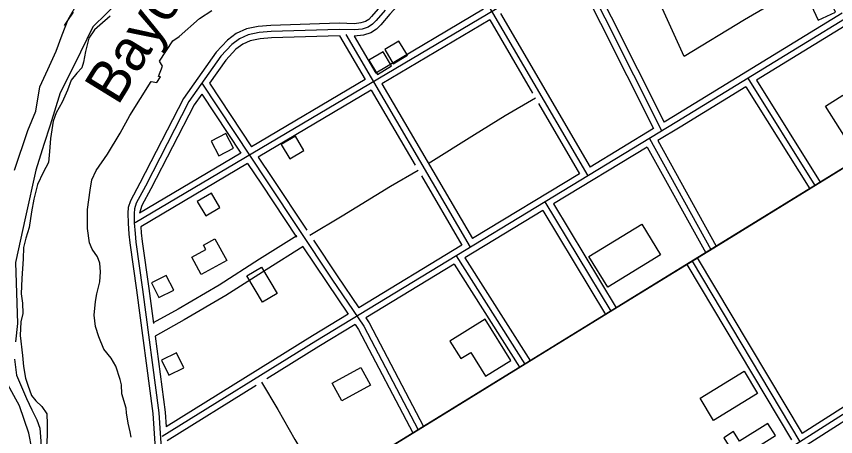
# Model space of a CAD drawing. Extents: x 3297772 to 3335630, y 634068 to 659439.
# Drawn here: x 3308401 to 3310382, y 649082 to 650098 of the extents above; entities that cross this region are included whole.
import ezdxf

# ---------------------------------------------------------------- set-up
doc = ezdxf.new("R2010")
doc.units = 0
for name, color, linetype in [('V-BLDG-OTLN', 7, 'Continuous'), ('V-DTCH-CNTR', 7, 'Continuous'), ('V-RIVR-IDEN', 7, 'Continuous'), ('V-ROAD-CNTR', 7, 'Continuous'), ('V-SITE-OTLN', 7, 'Continuous'), ('V-SITE-VEGE', 7, 'Continuous'), ('V-TOPO-SHOR', 7, 'Continuous')]:
    doc.layers.add(name, color=color, linetype=linetype)

msp = doc.modelspace()

# ---------------------------------------------------------------- linework, layer by layer
at = {"layer": 'V-BLDG-OTLN'}
for points in [[(3310300.2693621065, 650174.3976244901), (3310339.004284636, 650089.4497943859), (3310381.238200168, 650108.7077558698), (3310342.503277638, 650193.655585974)], [(3309312.2503381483, 649983.817005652), (3309346.6042694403, 650004.3049646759), (3309326.1163104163, 650038.6598959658), (3309291.7623791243, 650018.1719369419)], [(3309273.926414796, 649958.0390572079), (3309308.2803460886, 649978.527016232), (3309287.792387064, 650012.8819475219), (3309253.4384557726, 649992.393988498)], [(3310536.719889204, 649841.0272912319), (3310426.5151096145, 649771.591430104), (3310357.2882480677, 649881.4642103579), (3310399.2181642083, 649907.882157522), (3310430.605101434, 649858.066257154), (3310498.8809648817, 649901.084171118)], [(3308890.806181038, 649760.702451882), (3308926.246110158, 649779.2484147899), (3308907.6991472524, 649814.6893439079), (3308872.259218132, 649796.142381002)], [(3309076.1628103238, 649808.5883561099), (3309041.6768792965, 649788.322396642), (3309061.941838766, 649753.8364656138), (3309096.428769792, 649774.1014250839)], [(3308873.121216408, 649670.5426322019), (3308838.6352853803, 649650.2766727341), (3308858.90024485, 649615.7907417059), (3308893.387175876, 649636.0557011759)], [(3309958.355045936, 649521.1839309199), (3309830.670301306, 649443.2360868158), (3309785.346391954, 649517.479938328), (3309913.030136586, 649595.4277824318)], [(3308909.7231432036, 649507.71395786), (3308848.24026617, 649473.94902539), (3308825.0623125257, 649516.1549409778), (3308859.012244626, 649534.7989036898), (3308853.277256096, 649545.241882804), (3308880.8102010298, 649560.3618525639)], [(3308993.54497556, 649491.5009902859), (3309031.3838998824, 649427.7011178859), (3308996.0379705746, 649406.7381598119), (3308958.1990462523, 649470.5380322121)], [(3308727.9005068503, 649453.8840655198), (3308745.746471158, 649418.086137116), (3308781.544399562, 649435.9311014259), (3308763.699435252, 649471.7300298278)], [(3309596.23877017, 649265.5584421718), (3309534.045894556, 649365.5672421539), (3309449.310064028, 649312.872347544), (3309475.60401144, 649270.5894321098), (3309499.49896365, 649285.448402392), (3309535.394891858, 649227.7235178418)], [(3308752.28045809, 649266.378440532), (3308770.1264223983, 649230.5805121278), (3308805.924350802, 649248.4254764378), (3308788.079386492, 649284.22440484)], [(3309257.065448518, 649206.627560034), (3309188.227586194, 649168.6956358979), (3309164.818633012, 649211.1775509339), (3309233.656495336, 649249.10947507)], [(3310193.070576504, 649186.2706007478), (3310086.691789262, 649121.062731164), (3310053.806855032, 649174.710623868), (3310160.185642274, 649239.9184934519)], [(3310218.0345265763, 649113.8327456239), (3310149.2906640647, 649070.8638315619), (3310134.761693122, 649094.106785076), (3310110.9797406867, 649079.2408148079), (3310157.84764695, 649004.263964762), (3310178.125606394, 649016.9389394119), (3310164.26763411, 649039.1098950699), (3310236.5144896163, 649084.2678047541)]]:
    msp.add_lwpolyline(points, close=True, dxfattribs=at)
at = {"layer": 'V-DTCH-CNTR'}
msp.add_lwpolyline([(3308538.738, 650108.683), (3308524.932, 650088.662), (3308516.4960000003, 650076.343)], dxfattribs=at)
at = {"layer": 'V-ROAD-CNTR'}
for points in [[(3312568.9648247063, 651419.2411347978), (3311740.8984808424, 650919.1061350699), (3310719.21652421, 650286.2024008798), (3309997.8719669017, 649843.5352862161), (3309124.83971297, 649312.9013474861), (3308753.5614555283, 649081.90480948)], [(3312695.4435717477, 651149.2656747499), (3311525.301912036, 650438.1720969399), (3310854.68125328, 650011.558950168), (3309964.594033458, 649463.1000470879), (3308763.833434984, 648723.4155264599)], [(3312939.259084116, 650719.7405338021), (3312147.8886668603, 650226.4545203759), (3311603.3287559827, 649890.6091920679), (3310922.80111704, 649468.348036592), (3310057.579847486, 648917.3251386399), (3309400.102162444, 648502.041969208), (3308809.789343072, 648126.674719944), (3308064.599833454, 647651.8196696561), (3307615.6257314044, 647365.3602425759), (3307608.5777455, 647358.1752569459), (3307605.153752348, 647352.5692681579), (3307604.129754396, 647346.629280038), (3307606.361749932, 647341.7572897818), (3307617.461727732, 647320.5463322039), (3307621.65271935, 647311.931349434), (3307623.69271527, 647303.7813657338), (3307622.4197178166, 647297.7103778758), (3307620.646721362, 647291.379390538), (3307614.8467329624, 647284.846403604), (3307604.638753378, 647278.2334168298), (3306995.5399715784, 646891.920189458)], [(3308752.507457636, 648666.5346402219), (3308768.289426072, 648701.1635709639), (3308774.102414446, 648727.3205186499), (3308854.756253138, 648778.183416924), (3309003.575955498, 648871.1002310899), (3309462.9030368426, 649154.052665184), (3309689.957582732, 649293.920385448), (3309910.267142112, 649429.6341140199), (3310107.8487469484, 649551.3718705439), (3310370.686221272, 649713.3285466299), (3310640.1676823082, 649879.3792145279), (3310865.89123086, 650018.689935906), (3311087.3317879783, 650159.5586541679), (3311313.702335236, 650303.5643661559), (3311454.208054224, 650392.9451873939), (3311582.125798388, 650472.7040278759), (3311736.615489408, 650566.5868401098), (3311915.161132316, 650675.088623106), (3312000.5909614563, 650727.004519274)], [(3309727.1325083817, 650621.3827305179), (3309855.7092512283, 650316.845339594), (3309858.022246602, 650307.566358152), (3309857.3322479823, 650304.026365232), (3309852.731257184, 650293.9893853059), (3309843.959274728, 650284.6304040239), (3308688.2105862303, 649598.730775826)], [(3309446.96906871, 650288.7063958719), (3309782.5763974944, 649712.6775479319)], [(3309445.3200720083, 650261.7404498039), (3309427.4661077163, 650238.240496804), (3309303.930354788, 650103.4887663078), (3309282.076398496, 650077.9678173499), (3309271.8344189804, 650067.4678383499), (3309257.726447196, 650058.8808555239), (3309240.385481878, 650053.0958670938), (3309217.877526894, 650050.4698723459)], [(3309755.2474521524, 650231.98250932), (3309961.2380401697, 649821.054331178)], [(3309774.91841281, 650226.2135208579), (3309967.2730281, 649842.489288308)], [(3309749.054464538, 650210.8645515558), (3309941.550079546, 649826.8563195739)], [(3309281.4743997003, 650123.386726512), (3309259.9224428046, 650098.219776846), (3309253.002456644, 650091.125791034), (3309245.020472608, 650086.2668007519), (3309233.831494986, 650082.533808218), (3309218.447525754, 650080.739811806), (3309181.400599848, 650081.6648099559), (3309016.166930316, 650076.509820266), (3308986.088990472, 650074.0018252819), (3308957.229048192, 650068.146836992), (3308932.963096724, 650057.2208588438), (3308911.7701391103, 650041.16289096), (3308884.124194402, 650011.5209502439), (3308805.602351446, 649900.067173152), (3308699.734563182, 649694.9775833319), (3308676.9696087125, 649652.3696685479), (3308671.822619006, 649636.0897011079), (3308670.657621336, 649622.1127290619), (3308671.1636203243, 649597.8727775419), (3308673.1256164, 649571.8668295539), (3308675.181612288, 649550.2618727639), (3308691.4425797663, 649435.773101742), (3308731.0315005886, 649137.6236980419), (3308740.609481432, 648991.5169902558)], [(3309292.702377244, 650113.4377464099), (3309270.9994206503, 650088.0937970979), (3309262.418437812, 650079.2968146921), (3309251.3734599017, 650072.573828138), (3309237.108488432, 650067.814837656), (3309219.132524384, 650065.7178418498), (3309181.447599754, 650066.658839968), (3309017.0249286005, 650061.5288502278), (3308988.210986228, 650059.1268550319), (3308961.857038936, 650053.779865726), (3308940.669081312, 650044.239884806), (3308921.858118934, 650029.986913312), (3308895.794171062, 650002.0419692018), (3308818.4583257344, 649892.2711887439), (3308713.014536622, 649688.002597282), (3308690.8535809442, 649646.524680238), (3308686.631589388, 649633.1697069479), (3308685.67059131, 649621.6447299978), (3308686.151590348, 649598.5937761), (3308688.071586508, 649573.1418270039), (3308690.081582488, 649552.027869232), (3308706.303550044, 649437.815097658), (3308745.9664707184, 649139.1026950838), (3308755.617451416, 648991.8879895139)], [(3309530.2819020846, 650115.9157414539), (3309269.8944228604, 649961.384050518)], [(3309571.182820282, 650105.3057626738), (3309787.844386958, 649733.4325064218)], [(3310397.51716761, 650106.384760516), (3309990.053982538, 649856.336260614), (3309967.2730281, 649842.489288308)], [(3309545.384871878, 650089.993793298), (3309285.0213926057, 649935.476102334)], [(3309545.382871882, 650089.993793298), (3309648.6587867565, 649912.7336634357)], [(3310404.715153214, 650075.603822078), (3310190.111582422, 649943.90808547)], [(3309182.42959779, 650051.681869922), (3309017.882926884, 650046.54788019), (3308990.332981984, 650044.2518847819), (3308966.48502968, 650039.41289446), (3308948.3750659, 650031.2589107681), (3308931.946098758, 650018.810935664), (3308907.4641477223, 649992.56298816), (3308867.9802266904, 649936.51810025)], [(3309182.42959779, 650051.681869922), (3309244.09447446, 649946.072081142)], [(3309197.998566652, 650054.7668637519), (3309498.5409655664, 649540.03889321)], [(3309217.877526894, 650050.4698723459), (3309269.893422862, 649961.38305052)], [(3309244.095474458, 649946.0730811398), (3308969.534023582, 649783.1304070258)], [(3310169.375623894, 649948.782075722), (3310331.614299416, 649689.2525947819)], [(3308849.816263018, 649936.7800997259), (3309006.1809502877, 649700.6055720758), (3309164.018634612, 649462.7830477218), (3309241.0794804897, 649348.9392754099), (3309372.525217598, 649098.3777765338)], [(3308867.979226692, 649936.517100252), (3308969.534023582, 649783.129407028)], [(3309285.0203926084, 649935.476102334), (3309503.796955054, 649560.7868517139)], [(3310164.541633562, 649928.216116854), (3310005.689951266, 649830.7343118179), (3309951.4770596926, 649797.7823777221)], [(3310164.541633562, 649928.2171168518), (3310318.8383249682, 649681.3916105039)], [(3310190.111582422, 649943.9090854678), (3310344.394273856, 649697.107579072)], [(3308849.431263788, 649910.190152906), (3308831.314300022, 649884.475204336), (3308726.2945100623, 649681.0276112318), (3308704.737553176, 649640.679691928), (3308699.0185646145, 649622.587728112)], [(3308849.431263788, 649910.190152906), (3308943.704075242, 649767.7994376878)], [(3309259.2224442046, 649920.165132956), (3308986.1149904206, 649758.0854571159)], [(3309259.2214442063, 649920.165132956), (3309365.5312364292, 649738.0920845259)], [(3309655.7991416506, 649900.4781415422), (3309582.829, 649857.476), (3309508.609, 649812.221), (3309396.805715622, 649741.37142523)], [(3309663.303262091, 649887.5982618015), (3309762.20343824, 649717.84853759)], [(3309941.550079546, 649826.8563195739), (3309787.844386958, 649733.4325064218)], [(3309931.375099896, 649803.11836705), (3310080.2128022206, 649534.3429046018)], [(3309951.4760596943, 649797.7833777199), (3310092.926776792, 649542.3458885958)], [(3308943.70507524, 649767.800437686), (3308699.0185646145, 649622.587728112)], [(3309925.820111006, 649782.1884089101), (3309699.3305639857, 649644.5266842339)], [(3309925.819111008, 649782.1884089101), (3310067.4678277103, 649526.392920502)], [(3308986.1149904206, 649758.0854571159), (3309018.683925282, 649708.8935555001), (3309103.5013239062, 649581.0941963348)], [(3308960.28504208, 649742.7554877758), (3308701.887558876, 649589.405794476)], [(3308960.28504208, 649742.7554877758), (3308993.677975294, 649692.3175886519), (3309078.474173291, 649564.5510229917)], [(3309110.993708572, 649569.2080000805), (3309188.433, 649615.75), (3309305.66, 649687.389), (3309372.7168153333, 649726.3903387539)], [(3309380.2151275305, 649712.9434998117), (3309478.1570063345, 649545.201882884)], [(3309762.2044382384, 649717.84853759), (3309503.796955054, 649560.7868517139)], [(3309678.772605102, 649649.5846741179), (3309838.054286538, 649385.1492029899)], [(3309673.6946152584, 649628.945715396), (3309484.951992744, 649514.2259448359)], [(3309673.69361526, 649628.9447153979), (3309825.2733121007, 649377.297218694)], [(3309699.3305639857, 649644.5266842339), (3309850.774261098, 649393.1021870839)], [(3308701.887558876, 649589.405794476), (3308703.017556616, 649574.4168244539), (3308704.9815526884, 649553.7938657), (3308721.164520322, 649439.8570935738), (3308732.382426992, 649355.3703372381)], [(3309078.810966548, 649567.1076163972), (3308989.044743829, 649510.722225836), (3308891.810838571, 649448.5592807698), (3308792.2404384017, 649389.967542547), (3308732.205029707, 649356.7063905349)], [(3309119.4209402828, 649557.1071747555), (3309176.4786096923, 649471.135031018), (3309228.89450486, 649393.7001858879)], [(3309094.444814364, 649541.5004176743), (3309005.103256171, 649485.3817741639), (3308907.5031614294, 649422.9847192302), (3308807.119561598, 649363.9144574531), (3308736.4467877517, 649324.7599330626)], [(3309094.067769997, 649541.055390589), (3309151.558659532, 649454.431064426), (3309203.227556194, 649378.0992170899)], [(3309478.1580063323, 649545.2028828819), (3309228.895504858, 649393.7001858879)], [(3309464.080034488, 649519.0939350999), (3309630.5477015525, 649257.3224586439)], [(3309484.9509927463, 649514.226944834), (3309643.91367482, 649264.2574447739)], [(3310047.238868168, 649514.0609451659), (3310300.384361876, 649089.7417938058)], [(3309459.3110440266, 649498.6419760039), (3309245.731471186, 649368.826235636)], [(3309459.3100440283, 649498.6419760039), (3309617.7527271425, 649249.48947431)], [(3310021.750919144, 649498.22897683), (3310275.069412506, 649073.620826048)], [(3310034.48289368, 649506.1649609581), (3310295.416371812, 649068.7928357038)], [(3310791.862378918, 649402.742167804), (3310300.385361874, 649089.7417938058)], [(3309203.22955619, 649378.100217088), (3309116.9817286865, 649325.6783219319), (3308763.1964362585, 649105.5657621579)], [(3309220.065522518, 649353.2262668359), (3309132.6976972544, 649300.1243730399), (3309006.337444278, 649221.5071959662)], [(3309220.063522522, 649353.227266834), (3309228.186506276, 649341.227290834), (3309359.64424336, 649090.6427920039)], [(3309245.730471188, 649368.8282356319), (3309253.9724547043, 649356.651259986), (3309385.1981922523, 649106.5087602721)], [(3308736.4747761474, 649324.5491407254), (3308760.9014408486, 649140.581692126), (3308763.1964362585, 649105.5657621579)], [(3308993.4169608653, 649213.4684978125), (3309033.2830000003, 649147.684), (3309074.1890000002, 649074.435), (3309144.3741436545, 648957.8340459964)], [(3308981.1340152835, 649205.8264546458), (3308765.422431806, 649071.6178300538)], [(3310462.1490383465, 649157.1946589), (3310199.2035642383, 648989.7359938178)]]:
    msp.add_lwpolyline(points, dxfattribs=at)
at = {"layer": 'V-SITE-OTLN'}
msp.add_lwpolyline([(3310348.162, 650199.7660000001), (3310161.554, 650089.801), (3310015.049, 650001.524), (3309915.051, 650223.658), (3309837.522, 650402.606), (3309754.568, 650592.351), (3309970.535, 650687.706), (3310105.517, 650746.627), (3310191.566, 650552.256), (3310298.545, 650313.15)], close=True, dxfattribs=at)
at = {"layer": 'V-SITE-VEGE'}
for points in [[(3308396.664, 649726.737), (3308428.596, 649822.598), (3308448.247, 649869.301), (3308458.071, 649928.2930000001), (3308477.722, 649970.079), (3308497.37, 650014.324), (3308512.108, 650053.652), (3308526.845, 650090.522), (3308551.409, 650134.765)], [(3308652.113, 650137.22), (3308585.795, 650073.312), (3308541.582, 649982.367), (3308507.194, 649913.542), (3308482.633, 649834.888), (3308467.895, 649788.186), (3308448.245, 649726.735), (3308423.683, 649613.665), (3308399.119, 649503.057), (3308404.035, 649355.578), (3308399.119, 649311.333)], [(3308396.664, 649269.5480000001), (3308401.577, 649230.22), (3308426.139, 649173.687), (3308438.421, 649146.65), (3308450.7, 649122.0700000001), (3308458.0670000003, 649102.405), (3308460.5270000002, 649070.452), (3308460.5270000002, 649040.954), (3308462.982, 649006.544), (3308462.982, 648984.421), (3308467.895, 648950.009), (3308477.722, 648915.596), (3308465.44, 648849.231), (3308453.1580000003, 648802.528), (3308445.789, 648777.948), (3308438.421, 648738.621), (3308423.681, 648691.92), (3308411.401, 648657.507), (3308399.119, 648635.387)], [(3308396.664, 648748.455), (3308411.401, 648768.118), (3308413.859, 648800.071), (3308421.2260000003, 648829.568), (3308428.594, 648856.606), (3308438.421, 648881.186), (3308448.245, 648915.596), (3308448.245, 648964.759), (3308443.3340000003, 649021.292), (3308438.421, 649053.245), (3308431.0500000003, 649090.115), (3308408.946, 649156.48), (3308377.0130000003, 649215.475)]]:
    msp.add_lwpolyline(points, dxfattribs=at)
at = {"layer": 'V-TOPO-SHOR'}
for points in [[(3308678.782, 649080.5380000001), (3308676.249, 649093.512), (3308671.163, 649114.279), (3308667.823, 649139.359), (3308667.014, 649150.596), (3308655.943, 649185.22), (3308655.181, 649206.828), (3308651.785, 649219.808), (3308641.566, 649251.835), (3308630.427, 649271.764), (3308612.38, 649293.456), (3308600.419, 649322.899), (3308592.7600000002, 649347.997), (3308589.436, 649375.667), (3308592.182, 649408.497), (3308595.7290000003, 649427.4940000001), (3308602.779, 649455.98), (3308604.622, 649480.171), (3308602.9960000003, 649501.783), (3308597.018, 649516.504), (3308584.144, 649535.579), (3308578.164, 649550.2980000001), (3308573.142, 649584.893), (3308573.363, 649631.561), (3308579.634, 649678.2000000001), (3308584.074, 649703.243), (3308594.552, 649725.662), (3308621.5300000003, 649765.289), (3308652.021, 649816.137), (3308675.556, 649858.373), (3308726.9390000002, 649941.096), (3308740.752, 649938.437), (3308749.461, 649952.224), (3308745.143, 649953.109), (3308754.771, 649978.125), (3308747.048, 649990.262), (3308779.259, 650039.371), (3308794.865, 650049.6680000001), (3308844.3340000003, 650093.51), (3308873.809, 650112.384)], [(3308628.299, 650098.855), (3308603.133, 650077.3690000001), (3308590.1180000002, 650066.196), (3308576.1920000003, 650045.5210000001), (3308568.262, 650013.58), (3308563.818, 649987.6730000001), (3308559.431, 649973.868), (3308547.27, 649960.961), (3308533.36, 649943.742), (3308524.602, 649919.585), (3308512.37, 649891.122), (3308497.554, 649865.2660000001), (3308490.542, 649844.557), (3308483.431, 649803.107), (3308481.551, 649771.138), (3308478.836, 649745.225), (3308465.757, 649721.087), (3308452.654, 649691.7660000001), (3308443.846, 649656.3740000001), (3308437.646, 649625.29), (3308432.2830000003, 649587.289), (3308424.386, 649562.265), (3308418.225, 649538.958), (3308418.098, 649512.166), (3308414.416, 649464.6510000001), (3308412.511, 649427.498), (3308415.862, 649405.011), (3308416.605, 649379.946), (3308412.188, 649359.224), (3308410.304, 649326.392), (3308416.124, 649277.9670000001), (3308418.588, 649251.1630000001), (3308423.642, 649223.485), (3308428.7460000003, 649206.175), (3308438.134, 649181.066), (3308448.443, 649168.053), (3308463.072, 649155.022), (3308475.086, 649136.8150000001), (3308475.8310000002, 649111.75), (3308475.7, 649084.094), (3308473.853, 649059.0380000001)]]:
    msp.add_lwpolyline(points, dxfattribs=at)

# ---------------------------------------------------------------- texts
at = {"layer": 'V-RIVR-IDEN'}
msp.add_text('Bayou', height=99.99980199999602, rotation=58.38800276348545, dxfattribs=at).set_placement((3308646.4329726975, 649880.3579698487))

doc.saveas('drawing.dxf')
